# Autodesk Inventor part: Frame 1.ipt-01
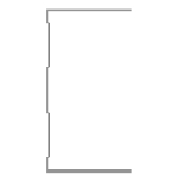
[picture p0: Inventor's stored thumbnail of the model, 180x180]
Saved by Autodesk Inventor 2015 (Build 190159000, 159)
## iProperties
IsCustomPart: 1
Created: 2015-04
Part Number: Frame 1.ipt-01
Material: Aluminum 6061
Description: Kévin Novo
Document SubType Name: Modeling
Standard: Kevin
Designer: suporte
Standards Organization: Kevin
Language: en-US
Size Designation: (Unnamed 1)
Categories: <MemberInstance><Categories><Category DisplayName="Structural Shapes" InternalName="089c4875-fa83-4c05-b084-43b9cc11f5ed" Mnemonic="GRDR"><CategoryParameter Dis
Density: 2.7 g/cm^3
Appearance: Aluminum - Flat
_CCFamilyMember: 1
_CCFamilyDisplayName: Kévin - Kévin Novo
_FrameMemberDoc: Frame Member File
_Version: 15.0.0
_GetPNFromCC: 1
G_L: 1086,186 mm
G_W: 50,000 mm
G_H: 75,000 mm
+BC625CA7-C02F-465B-8547-A92C4635F835+CUTDETAIL1: Cut
+90C232A2-F113-4F90-9BE8-95EAE997F2A7+CUTDETAIL2: Cut
Author: suporte
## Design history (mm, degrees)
node "Start Plane"
node "End Plane"
sketch "Sketch"
  geometry: L1 (24.7, 37.5)-(24.7, 36.9); L2 (24.7, 36.9)-(-24.7, 36.9); L3 (-24.7, -36.9)-(24.7, -36.9); L4 (24.7, -36.9)-(24.7, -37.5); L5 (24.7, -37.5)-(-25.3, -37.5); L6 (-25.3, 37.5)-(24.7, 37.5); L7 (-24.7, 36.9)-(-24.7, 31.9); L8 (-24.7, 31.9)-(-23.3, 30.5); L9 (-23.3, 30.5)-(-23.3, 10.934); L10 (-23.3, 10.934)-(-24.7, 9.534); L11 (-24.7, 9.534)-(-24.7, -9.534); L12 (-24.7, -9.534)-(-23.3, -10.934); L13 (-23.3, -10.934)-(-23.3, -30.5); L14 (-23.3, -30.5)-(-24.7, -31.9); L15 (-24.7, -31.9)-(-24.7, -36.9); L16 (-25.3, -37.5)-(-25.3, -31.651); L17 (-25.3, -31.651)-(-23.9, -30.251); L18 (-23.9, -30.251)-(-23.9, -11.183); L19 (-23.9, -11.183)-(-25.3, -9.783); L20 (-25.3, -9.783)-(-25.3, 9.783); L21 (-25.3, 9.783)-(-23.9, 11.183); L22 (-23.9, 11.183)-(-23.9, 30.251); L23 (-23.9, 30.251)-(-25.3, 31.651); L24 (-25.3, 31.651)-(-25.3, 37.5); L25 (-25.3, 0)-(30.37, 0); 3 further points
  constraints: 50 end point, 10 point on line, 9 parallel, 5 perpendicular, 4 equal length, 3 midpoint, 3 vertical, 2 vertical alignment, 1 collinear, 1 horizontal, 1 horizontal alignment
  dimensions: "d3" = 0.6 distance of L1.start L1.end (= d6); "d5" = 75 distance between parallel lines of L5 L6; "d6" = 0.6 distance between parallel lines of L24 L7 (= d8); "d7" = 0.6 distance between parallel lines of L8 L23 (= d8); "d8" = 0.6 distance between parallel lines of L22 L9 (= d12); "Espessura" = 0.6 distance between parallel lines of L17 L14; "d10" = 0.6 distance between parallel lines of L13 L18 (= Espessura); "d11" = 0.6 distance between parallel lines of L12 L19 (= Espessura); "d12" = 0.6 distance between parallel lines of L21 L10 (= d11); "d13" = 5 distance of L2.end L7.end; "d15" = 135 deg angle of L9 L8; "d16" = 2 distance between parallel lines of L24 L9; "d17" = 50 distance of L6.start L1.start
extrude "Body" join sketch "Sketch" stored distance "d24" = 0.13; taper "d25" = 0 deg
node "Driven Length"
  sketch "Sketch10"
    geometry: L1 (0, 0)-(10, 0) reference
    constraints: 2 end point, 1 horizontal
  workplane "Work Plane7"
  sketch "Sketch11"
    geometry: L1 (-2, 12.5)-(12, 12.5) reference; L2 (-2, 1098.686)-(12, 1098.686) reference
    dimensions: "d27" = 1086.1863 distance between parallel lines of L1 L2 (derived)
workplane "Work Plane8"
split "Split1"
workplane "Work Plane9"
split "Split2"
body "Solid1"
other parameters: "tamanho" = 1018.55826, "G_OFFSET_START" = -12.5 [user parameter; used in 1 equation term], "G_OFFSET_END" = 80.12804 [user parameter; used in 1 equation term], "d22" = 12.5 (= -G_OFFSET_START), "d23" = 1098.6863 (= tamanho + G_OFFSET_END), "G_L" = 1086.1863 (= d27) [user parameter], "d34" = 90 deg
